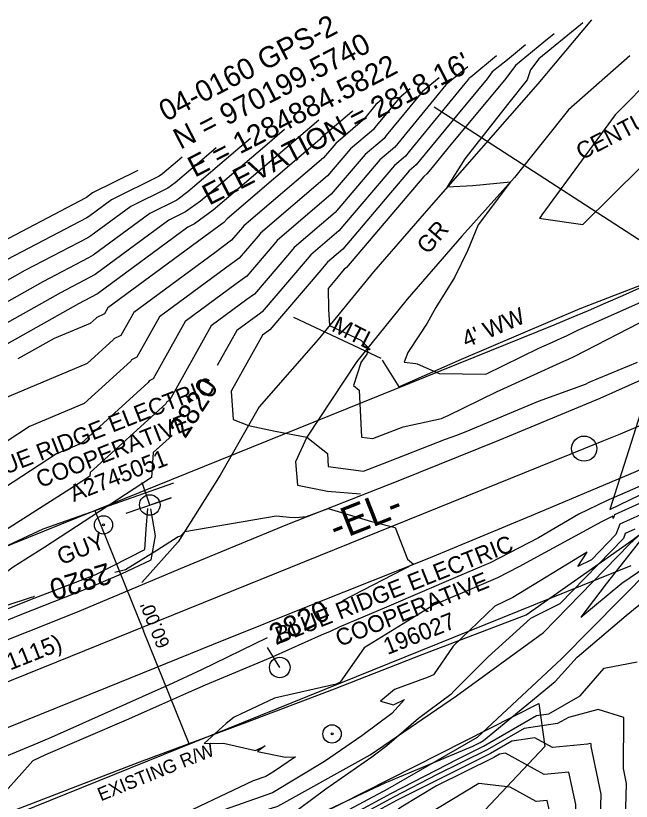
# Model space of a CAD drawing. Extents: x 1284446 to 1285480, y 969739 to 970628.
# Drawn here: x 1284710.8 to 1284857.4, y 970083.4 to 970270.6 of the extents above; entities that cross this region are included whole.
import ezdxf

# ---------------------------------------------------------------- set-up
doc = ezdxf.new("R2010")
doc.units = 0
for name, color, linetype in [('CTL Primary Horizontal and Vertical Leader', 7, 'Continuous'), ('CTL Primary Horizontal and Vertical Text', 7, 'Continuous'), ('Default', 7, 'Continuous'), ('Exist Horizontal Alignment', 7, 'Continuous'), ('Exist Horizontal Alignment Direction Label', 7, 'Continuous'), ('Exist Horizontal Alignment Point', 7, 'Continuous'), ('Exist Hydro Jurisdictional Stream or Body of Water', 7, 'Continuous'), ('Exist Other Culture Anchor (Guy Wire) CELL', 7, 'Continuous'), ('Exist Other Culture Fence Line', 7, 'Continuous'), ('Exist Other Culture Fence Line Text', 7, 'Continuous'), ('Exist Other Culture Gate', 7, 'Continuous'), ('Exist Other Culture Gate Text', 7, 'Continuous'), ('Exist Other Culture Located Object Text', 7, 'Continuous'), ('Exist Right of Way Line', 7, 'Continuous'), ('Exist Right of Way Line Text', 7, 'Continuous'), ('Exist Right of Way Width CELL', 7, 'Continuous'), ('Exist Roads EOP', 7, 'Continuous'), ('Exist Roads EOP Text', 7, 'Continuous'), ('Exist Roads Soil', 7, 'Continuous'), ('Exist Roads Soil Text', 7, 'Continuous'), ('Exist Utilities Power Joint Use Telephone CELL', 7, 'Continuous'), ('Exist Utilities Power Joint Use Telephone Text', 7, 'Continuous'), ('Exist Utilities Power Pole CELL', 7, 'Continuous'), ('Exist Utilities Power Pole Text', 7, 'Continuous'), ('Exist Utilities Telephone Pole Text', 7, 'Continuous'), ('Exist Utilities Telephone UG Cable SUE LOS D', 7, 'Continuous'), ('Exist Vegetation Woods Line', 7, 'Continuous')]:
    doc.layers.add(name, color=color, linetype=linetype)

msp = doc.modelspace()

# ---------------------------------------------------------------- linework, layer by layer
at = {"layer": 'CTL Primary Horizontal and Vertical Leader'}
msp.add_line((1284882.18, 970202.31), (1284810.44, 970248.87), dxfattribs=at)
at = {"layer": 'Default'}
for points in [[(1284845.89, 970268.91), (1284845.33, 970268.46), (1284835.4, 970260.35), (1284833.44, 970257.71), (1284832.64, 970255.39), (1284827.89, 970249.49), (1284817.77, 970236.54), (1284813.59, 970229.83), (1284819.68, 970230.14), (1284828.68, 970231.07), (1284820.96, 970220.8), (1284818.37, 970214.62), (1284815.31, 970208.23), (1284810.87, 970201.12), (1284808.77, 970197.34), (1284804.53, 970190.84), (1284804.16, 970190.36), (1284803.35, 970188.1), (1284806.1, 970187.73), (1284806.39, 970187.69), (1284811.67, 970185.39), (1284822.75, 970185.21), (1284835.4, 970191.39), (1284837.95, 970192.55), (1284841.62, 970194.18), (1284841.82, 970194.28), (1284844.67, 970195.74), (1284869.18, 970206.6)], [(1284839.04, 970266.29), (1284836.61, 970264.31), (1284829.85, 970258.79), (1284827.54, 970255.68), (1284813.75, 970239.1), (1284809.97, 970234.48), (1284808.72, 970232.97), (1284807.97, 970232.34), (1284789.57, 970210.67), (1284789.04, 970210.21), (1284787.21, 970208), (1284785.2, 970205.66), (1284785.26, 970200.75), (1284785.53, 970196.81), (1284793.01, 970193.3), (1284794.77, 970191.58), (1284794.41, 970189.99), (1284792.99, 970188.03), (1284792.98, 970187.94), (1284791.25, 970182.51), (1284792.61, 970181.44), (1284793.11, 970170.24), (1284795.87, 970169.86), (1284803.06, 970172.65), (1284812.24, 970174.65), (1284812.72, 970174.89), (1284813.81, 970175.39), (1284825.34, 970181.03), (1284841.34, 970188.29), (1284842.5, 970188.8), (1284843.81, 970189.47), (1284862.01, 970198.79)], [(1284832.19, 970263.67), (1284827.89, 970260.16), (1284824.3, 970257.24), (1284823.08, 970255.59), (1284815.77, 970246.8), (1284807.24, 970236.37), (1284806.17, 970235.08), (1284804.48, 970233.65), (1284788.67, 970215.03), (1284785.05, 970211.93), (1284783.47, 970210.02), (1284771.27, 970195.78), (1284770.98, 970195.57), (1284769.6, 970194.54), (1284762.1, 970181.14), (1284762.58, 970174.45), (1284766.24, 970173), (1284772.58, 970171.62), (1284780.12, 970170.21), (1284780.13, 970170.2), (1284785.05, 970166.35), (1284785.19, 970163.25), (1284793.63, 970162.11), (1284798.15, 970163.86), (1284813.18, 970169.72), (1284815.88, 970170.66), (1284818.12, 970171.59), (1284835.35, 970178.78), (1284846.49, 970182.87), (1284847.39, 970183.34), (1284858.91, 970188.12)], [(1284825.33, 970261.06), (1284819.16, 970256.02), (1284818.75, 970255.68), (1284818.61, 970255.5), (1284817.78, 970254.5), (1284804.52, 970238.27), (1284803.62, 970237.19), (1284800.99, 970234.96), (1284787.76, 970219.38), (1284781.06, 970213.66), (1284779.73, 970212.05), (1284769.46, 970200.05), (1284768.42, 970199.29), (1284763.45, 970195.63), (1284758.78, 970187.27)], [(1284818.48, 970258.44), (1284813.21, 970254.13), (1284801.79, 970240.16), (1284801.07, 970239.3), (1284797.5, 970236.28), (1284786.85, 970223.74), (1284777.07, 970215.38), (1284775.99, 970214.07), (1284767.64, 970204.32), (1284765.86, 970203.01), (1284757.3, 970196.71), (1284747.37, 970178.93), (1284746.78, 970178.64), (1284746.5, 970178.13), (1284728.47, 970161.78), (1284728.41, 970160.88), (1284726.52, 970159.64), (1284724.54, 970158.35), (1284703.64, 970145.09)], [(1284863.19, 970256.67), (1284853.55, 970247.05), (1284836.13, 970223.15), (1284835.89, 970222.82), (1284835.88, 970222.81), (1284835.56, 970222.37), (1284836.53, 970222.24), (1284845.9, 970220.91), (1284859.84, 970234.71)], [(1284811.63, 970255.82), (1284807.66, 970252.58), (1284799.06, 970242.06), (1284798.52, 970241.41), (1284794.01, 970237.59), (1284785.94, 970228.09), (1284773.09, 970217.1), (1284772.25, 970216.1), (1284765.83, 970208.59), (1284763.3, 970206.73), (1284751.16, 970197.79), (1284743.51, 970184.1), (1284742.57, 970183.64), (1284742.36, 970183.24), (1284726.36, 970168.74), (1284720.49, 970166.27), (1284697.97, 970151.55)], [(1284804.78, 970253.2), (1284802.11, 970251.02), (1284796.33, 970243.96), (1284795.97, 970243.52), (1284790.52, 970238.9), (1284785.04, 970232.45), (1284769.1, 970218.82), (1284768.52, 970218.12), (1284764.01, 970212.86), (1284760.74, 970210.45), (1284745.01, 970198.87), (1284739.64, 970189.26), (1284738.36, 970188.63), (1284738.21, 970188.36), (1284727.07, 970178.26), (1284714.06, 970172.78), (1284700.58, 970163.97)], [(1284797.93, 970250.58), (1284796.56, 970249.47), (1284793.61, 970245.85), (1284793.42, 970245.63), (1284787.02, 970240.21), (1284784.13, 970236.8), (1284765.11, 970220.55), (1284764.78, 970220.14), (1284762.2, 970217.13), (1284758.18, 970214.17), (1284738.87, 970199.95), (1284735.78, 970194.43), (1284734.15, 970193.63), (1284734.06, 970193.48), (1284727.79, 970187.79), (1284707.63, 970179.29)], [(1284791.08, 970247.96), (1284791.01, 970247.91), (1284790.88, 970247.75), (1284790.87, 970247.74), (1284783.53, 970241.52), (1284783.22, 970241.16), (1284761.12, 970222.27), (1284761.04, 970222.17), (1284760.38, 970221.4), (1284755.62, 970217.9), (1284732.72, 970201.03), (1284731.92, 970199.6), (1284729.94, 970198.63), (1284729.92, 970198.59), (1284728.51, 970197.31), (1284719.91, 970193.69), (1284711.26, 970188.85)], [(1284782.99, 970245.74), (1284777.01, 970240.66), (1284757.78, 970224.29), (1284753.36, 970221.03), (1284751.76, 970220.24), (1284730.23, 970204.39), (1284728.57, 970203.46), (1284725.7, 970201.95), (1284703.48, 970189.51)], [(1284774.84, 970243.54), (1284770.08, 970239.49), (1284754.77, 970226.46), (1284751.25, 970223.87), (1284747.23, 970221.88), (1284729.7, 970208.98), (1284728.36, 970208.22), (1284721.46, 970204.6), (1284702.83, 970194.17)], [(1284766.69, 970241.34), (1284763.15, 970238.33), (1284751.75, 970228.63), (1284749.13, 970226.7), (1284742.69, 970223.51), (1284729.18, 970213.57), (1284728.14, 970212.98), (1284717.21, 970207.24), (1284702.18, 970198.82)], [(1284758.54, 970239.14), (1284756.22, 970237.16), (1284748.74, 970230.8), (1284747.02, 970229.54), (1284738.16, 970225.14), (1284728.66, 970218.15), (1284727.93, 970217.74), (1284712.97, 970209.89), (1284701.53, 970203.48)], [(1284750.39, 970236.94), (1284749.29, 970236), (1284745.73, 970232.97), (1284744.91, 970232.37), (1284733.62, 970226.77), (1284728.14, 970222.74), (1284727.72, 970222.5), (1284708.72, 970212.53), (1284700.87, 970208.14), (1284698.91, 970206.2), (1284696.12, 970203.72), (1284683.01, 970190.92), (1284669.6, 970179.36)], [(1284739.84, 970233.74), (1284729.08, 970228.4), (1284727.62, 970227.33), (1284727.51, 970227.26), (1284704.48, 970215.18), (1284700.22, 970212.79), (1284697.9, 970210.5), (1284696.24, 970209.02), (1284680.37, 970193.53), (1284669.07, 970183.79), (1284663.63, 970178.84), (1284655.84, 970171.76), (1284643.02, 970159.37), (1284642.05, 970158.93), (1284625.37, 970148.84), (1284617.73, 970145.52), (1284604.5, 970139.27), (1284601.13, 970138.8), (1284580.23, 970128.69), (1284573.36, 970127.93), (1284568.84, 970128.73)], [(1284748.03, 970170.64), (1284743.49, 970166.53), (1284743.11, 970160.61), (1284730.72, 970152.47), (1284717.68, 970144.01), (1284710.17, 970139.24), (1284709.56, 970138.79), (1284691.19, 970125.24), (1284702.36, 970128.13), (1284714.55, 970132.09), (1284714.9, 970132.2), (1284715.19, 970132.29), (1284715.26, 970132.31)], [(1284860.83, 970159.08), (1284851.5, 970155.03), (1284844.93, 970151.86), (1284835.32, 970146.2), (1284823.82, 970140.28), (1284822.27, 970139.61), (1284815.57, 970136.76), (1284799.1, 970129.73), (1284787.86, 970124.9), (1284785.7, 970123.93), (1284783.51, 970123.01), (1284771.83, 970117.8), (1284755.92, 970111.13), (1284751.92, 970109.35), (1284745.5, 970106.55), (1284737.05, 970102.79), (1284717.87, 970094.48), (1284714.86, 970093.11), (1284708.34, 970085.8)], [(1284865.15, 970152.41), (1284863.74, 970150.95), (1284858.15, 970143.83), (1284857.93, 970143.55), (1284851.44, 970135.29), (1284845.39, 970127.31), (1284855.19, 970135.46), (1284860.88, 970139.28), (1284861.21, 970139.54), (1284870.02, 970144.7), (1284875.33, 970148.62), (1284884.51, 970153.12), (1284887.68, 970155.16), (1284888.77, 970156.05), (1284888.78, 970156.01), (1284890.6, 970152.24), (1284888.81, 970146.6), (1284891.3, 970150.92), (1284891.58, 970151.55)], [(1284859.37, 970154.43), (1284853.43, 970151.74), (1284853.08, 970150.83), (1284853.01, 970151.39), (1284850.35, 970150), (1284830.62, 970139.32), (1284825.53, 970136.69), (1284817.17, 970133.11), (1284816.66, 970132.89), (1284815.43, 970132.37), (1284810.33, 970130.17), (1284793.78, 970119.98), (1284788.05, 970111.8), (1284787.12, 970111.33), (1284772.41, 970108.01), (1284762.81, 970103.53), (1284760.88, 970101.98), (1284755.64, 970097.22), (1284760.29, 970097.26), (1284767.89, 970095.53), (1284770.17, 970096.68), (1284768.37, 970095.35), (1284775.02, 970093.93), (1284777.42, 970094.05), (1284772.44, 970090.62), (1284770.32, 970089.35), (1284767.37, 970088.3), (1284746.65, 970078.45)], [(1284734.41, 970138.02), (1284736.92, 970138.68), (1284744.35, 970143.25), (1284749.48, 970146.58), (1284750.13, 970146.71), (1284751.04, 970147.76), (1284772.82, 970151.48), (1284776.02, 970151.12), (1284777.51, 970151.04), (1284780.08, 970151.33), (1284785.19, 970153.22), (1284795.55, 970150.1), (1284801.18, 970148.68), (1284804.12, 970141.13), (1284805.57, 970139.95), (1284788.59, 970131.25)], [(1284859.6, 970151.72), (1284854.71, 970149.49), (1284853.74, 970146.99), (1284847.92, 970141), (1284844.71, 970139.39), (1284846.93, 970142.78), (1284829.23, 970131.97), (1284824.92, 970129.98), (1284814.97, 970120.43), (1284810.29, 970113.61), (1284809.06, 970113.04), (1284801.01, 970110.11), (1284797.67, 970107.34), (1284800.75, 970106.41), (1284803.41, 970107.68), (1284800.35, 970104.39), (1284793.21, 970099.03), (1284784.32, 970092.92), (1284771.92, 970085.47), (1284754.76, 970079.39)], [(1284858.27, 970148.29), (1284855.99, 970147.25), (1284855.54, 970146.09), (1284840.4, 970130.49), (1284833.4, 970126.99), (1284823.3, 970117.89), (1284815.21, 970109.79), (1284814.41, 970108.93), (1284806.71, 970103.16), (1284799.18, 970096.63), (1284795.58, 970093.93), (1284784.68, 970086.3), (1284775.07, 970079.22)], [(1284782.76, 970080.33), (1284798.81, 970087.84), (1284819.64, 970096.55), (1284821.27, 970097.39), (1284821.41, 970097.46), (1284822.19, 970097.92), (1284839.25, 970112.01), (1284844.55, 970117.79), (1284856.22, 970127.75), (1284864.85, 970134.79)], [(1284770.67, 970122.38), (1284755.04, 970114.8), (1284747.18, 970111.12), (1284744.66, 970109.99), (1284744.6, 970109.97), (1284719.18, 970098.66), (1284717.11, 970097.76), (1284716.01, 970097.26), (1284707.63, 970093.8), (1284683.78, 970082.51), (1284682.67, 970081.27), (1284681.13, 970080.8), (1284680.2, 970080.2)], [(1284781.36, 970075.12), (1284800.31, 970085.41), (1284816.16, 970093.56), (1284822.23, 970096.58), (1284834.81, 970103.89), (1284837.78, 970104.31), (1284845.27, 970108.59), (1284850.95, 970115.2), (1284858.84, 970116.67)], [(1284855.82, 970070.4), (1284856.31, 970087.69), (1284855.55, 970091.25), (1284855.64, 970103.39), (1284849.51, 970105.3), (1284842.46, 970103.44), (1284839.88, 970101.97), (1284831.87, 970100.82), (1284823.05, 970095.69), (1284811.04, 970089.73), (1284800.91, 970084.52), (1284788.79, 970077.94)], [(1284849.79, 970068.77), (1284850.26, 970085.18), (1284847.87, 970096.47), (1284847.87, 970097.12), (1284847.55, 970097.22), (1284846.98, 970097.07), (1284838.62, 970096.24), (1284834.42, 970098.54), (1284828.94, 970097.75), (1284823.87, 970094.81), (1284805.92, 970085.9), (1284801.51, 970083.63), (1284796.23, 970080.76)], [(1284842, 970058.21), (1284842.75, 970060.15), (1284843.9, 970062.31), (1284843.91, 970072.05), (1284844.21, 970082.67), (1284842.57, 970090.4), (1284836.68, 970089.82), (1284827.42, 970094.89), (1284826, 970094.69), (1284824.69, 970093.92), (1284811.04, 970087.15), (1284802.57, 970082.04), (1284785.82, 970069.23), (1284784.71, 970068.14)], [(1284835.1, 970054.15), (1284836.25, 970057.13), (1284838.01, 970060.43), (1284838.02, 970075.34), (1284838.16, 970080.15), (1284837.41, 970083.66), (1284834.74, 970083.4), (1284828.56, 970086.79), (1284821.11, 970087.68), (1284805.22, 970078.1), (1284794.34, 970069.77), (1284785.7, 970061.35), (1284779.71, 970059.61), (1284777.89, 970059.07), (1284758.44, 970049.57), (1284755.9, 970048.46), (1284748.28, 970046.25), (1284727.72, 970037.01), (1284725.28, 970036.25), (1284723.69, 970035.84), (1284717.37, 970033.86), (1284695.06, 970028.05)]]:
    msp.add_lwpolyline(points, dxfattribs=at)
at = {"layer": 'Exist Horizontal Alignment'}
msp.add_line((1284591.83, 970064.7), (1284846.18, 970167.48), dxfattribs=at)
msp.add_arc((1284607.88, 970757.2), 636.05, 292.00278, 305.45278, dxfattribs=at)
at = {"layer": 'Exist Horizontal Alignment Point'}
msp.add_circle((1284846.18, 970167.48), 3, dxfattribs=at)
at = {"layer": 'Exist Hydro Jurisdictional Stream or Body of Water'}
for points in [[(1284608.58, 970014.06), (1284652.45, 970028.03), (1284689.07, 970040.96), (1284720.23, 970048.49), (1284751.74, 970066.17), (1284777.43, 970074.66), (1284799.45, 970086.45), (1284820.82, 970098.72), (1284840.81, 970117.42), (1284861.95, 970138.73), (1284875.04, 970148.73), (1284887.31, 970157.71)], [(1284608.31, 970022.37), (1284646.2, 970034.88), (1284690.96, 970050.11), (1284715.91, 970057.86), (1284748.8, 970074.52), (1284773.24, 970082.29), (1284795.23, 970094.54), (1284815.77, 970108.56), (1284836.54, 970123.66), (1284856.99, 970144.69), (1284864.89, 970151.94), (1284873.19, 970156.9)]]:
    msp.add_lwpolyline(points, dxfattribs=at)
at = {"layer": 'Exist Other Culture Anchor (Guy Wire) CELL'}
for centre, radius in [((1284731.68, 970149.31), 2.18), ((1284731.68, 970149.31), 0.24), ((1284786.13, 970099.5), 2.18), ((1284786.13, 970099.5), 0.24)]:
    msp.add_circle(centre, radius, dxfattribs=at)
at = {"layer": 'Exist Other Culture Fence Line'}
for points in [[(1284798.04, 970188.58), (1284802.02, 970182.24), (1284816.97, 970188.81), (1284845.25, 970200.84), (1284869.92, 970210.38), (1284879.4, 970214.23), (1284891.22, 970210.43)], [(1284748.36, 970159.23), (1284717.21, 970148.3), (1284693.29, 970137.2), (1284650.97, 970121.07)], [(1284601.96, 970038.43), (1284640.3, 970053.54), (1284684.75, 970071.66), (1284706.29, 970079.75), (1284740.35, 970092.84), (1284765.34, 970102.18), (1284786.69, 970110.23), (1284807.57, 970118.44), (1284832.39, 970127.91), (1284856.77, 970145.02), (1284872.83, 970156.87)]]:
    msp.add_lwpolyline(points, dxfattribs=at)
at = {"layer": 'Exist Other Culture Gate'}
msp.add_line((1284776.94, 970198.78), (1284797.76, 970189.02), dxfattribs=at)
at = {"layer": 'Exist Other Culture Located Object Text'}
for p, q in [((1284864.82, 970192.39), (1284852.28, 970153.01)), ((1284852.28, 970153.01), (1284909.05, 970180.44))]:
    msp.add_line(p, q, dxfattribs=at)
at = {"layer": 'Exist Right of Way Line'}
for p, q in [((1284580.59, 970092.51), (1284834.94, 970195.29)), ((1284603.06, 970036.88), (1284857.42, 970139.66))]:
    msp.add_line(p, q, dxfattribs=at)
msp.add_arc((1284607.88, 970757.2), 606.05, 292.00278, 305.45278, dxfattribs=at)
at = {"layer": 'Exist Right of Way Width CELL'}
for p in [(1284729.65, 970152.75), (1284752.13, 970097.12)]:
    msp.add_line(p, (1284741.23, 970124.08), dxfattribs=at)
at = {"layer": 'Exist Roads EOP'}
for points in [[(1284588.17, 970073.97), (1284609.91, 970082.54), (1284630.17, 970090.65), (1284654.44, 970100.5), (1284678.03, 970109.93), (1284701.92, 970119.24), (1284725.51, 970128.63), (1284750.96, 970139.34), (1284775.61, 970149.46), (1284801.89, 970159.77), (1284826.13, 970169.58), (1284850.02, 970179.49), (1284870.96, 970188.88), (1284892.26, 970198.92), (1284892.63, 970199.46)], [(1284594.23, 970054.93), (1284616.52, 970063.71), (1284637.53, 970072.23), (1284661.54, 970081.97), (1284684.2, 970091.02), (1284708.29, 970100.77), (1284732.61, 970110.68), (1284757.85, 970120.85), (1284782.44, 970130.77), (1284809.22, 970141.4), (1284833.63, 970151.55), (1284857.38, 970161.54), (1284879.44, 970171.07), (1284883.53, 970171.7)]]:
    msp.add_lwpolyline(points, dxfattribs=at)
at = {"layer": 'Exist Roads Soil'}
for points in [[(1284847.92, 970269.69), (1284835.17, 970254.44), (1284821.63, 970238.99), (1284808.61, 970224.15), (1284796.03, 970209.59), (1284782.81, 970193.51), (1284768.73, 970177.4), (1284759.51, 970161.13), (1284749.49, 970145.31), (1284740.82, 970135.59)], [(1284857.11, 970261.11), (1284842.43, 970248.21), (1284829.57, 970232.07), (1284817.04, 970218.11), (1284804.05, 970203.09), (1284792.06, 970188.21), (1284780.13, 970170.23), (1284777.45, 970164.32), (1284777.92, 970158.77), (1284785.08, 970157.31), (1284792.88, 970156.68)]]:
    msp.add_lwpolyline(points, dxfattribs=at)
at = {"layer": 'Exist Utilities Power Joint Use Telephone CELL'}
msp.add_line((1284742.71, 970154.05), (1284742.71, 970154.05), dxfattribs=at)
msp.add_lwpolyline([(1284737.1, 970152.11), (1284747.83, 970155.78), (1284742.72, 970154.03), (1284740.88, 970159.37)], dxfattribs=at)
msp.add_circle((1284742.71, 970154.06), 2.45, dxfattribs=at)
at = {"layer": 'Exist Utilities Power Pole CELL'}
for q in [(1284770.72, 970120.12), (1284773.68, 970115.33)]:
    msp.add_line((1284773.68, 970115.33), q, dxfattribs=at)
msp.add_circle((1284773.68, 970115.33), 2.45, dxfattribs=at)
at = {"layer": 'Exist Utilities Telephone UG Cable SUE LOS D'}
for points in [[(1284574.8, 970074.26), (1284594.5, 970082.54), (1284616.05, 970091.44), (1284632.57, 970100.26), (1284654.25, 970107.71), (1284668.02, 970113.22), (1284683.01, 970118.85), (1284698.34, 970125.18), (1284715.18, 970131.84), (1284729.87, 970137.49), (1284741.49, 970143.41), (1284741.82, 970148.26), (1284742.26, 970153.18)], [(1284576.08, 970071.21), (1284596.07, 970079.34), (1284617.42, 970089.61), (1284633.49, 970097.01), (1284654.93, 970104.42), (1284670.21, 970110.81), (1284685.4, 970117.07), (1284700.9, 970123.39), (1284712.2, 970128.05), (1284727.98, 970134.25), (1284736, 970137.68), (1284743.05, 970140.96), (1284744.07, 970146.74), (1284742.92, 970153.14)]]:
    msp.add_lwpolyline(points, dxfattribs=at)
at = {"layer": 'Exist Vegetation Woods Line'}
msp.add_lwpolyline([(1284756.79, 970066.82), (1284776.33, 970076.8), (1284835.4, 970106.74), (1284836.86, 970096.51), (1284812.24, 970070.36), (1284780.66, 970046.59), (1284759.93, 970045.08), (1284756.79, 970066.82)], dxfattribs=at)

# ---------------------------------------------------------------- texts
at = {"layer": 'CTL Primary Horizontal and Vertical Text'}
for s, p in [('04-0160 GPS-2', (1284746.56, 970245.33)), ('N = 970199.5740', (1284750, 970238.67)), ("ELEVATION = 2818.16'", (1284756.88, 970225.34)), ('E = 1284884.5822', (1284753.44, 970232.01))]:
    msp.add_text(s, height=5, rotation=27.3235, dxfattribs=at).set_placement(p)
at = {"layer": 'Default'}
for rotation, p in [(57.1183, (1284751.14, 970169.67)), (196.6108, (1284732.64, 970140.34)), (26.3241, (1284772.73, 970120.56))]:
    msp.add_text('2820', height=5, rotation=rotation, dxfattribs=at).set_placement(p)
at = {"layer": 'Exist Horizontal Alignment Direction Label'}
msp.add_text('-EL-', height=7, rotation=21.5608, dxfattribs=at).set_placement((1284787.06, 970145.26))
at = {"layer": 'Exist Other Culture Anchor (Guy Wire) CELL'}
msp.add_text('GUY', height=4, rotation=21.458, dxfattribs=at).set_placement((1284721.6, 970139.68))
at = {"layer": 'Exist Other Culture Fence Line Text'}
msp.add_text("4' WW", height=4, rotation=23.0478, dxfattribs=at).set_placement((1284818.13, 970191.47))
at = {"layer": 'Exist Other Culture Gate Text'}
msp.add_text('MTL', height=4, rotation=333.037, dxfattribs=at).set_placement((1284785.77, 970195.64))
at = {"layer": 'Exist Right of Way Line Text'}
msp.add_text('EXISTING R/W', height=3.2, rotation=22.0028, dxfattribs=at).set_placement((1284731.06, 970083.43))
at = {"layer": 'Exist Right of Way Width CELL'}
msp.add_text("60.00'", height=3.2, rotation=112.0028, dxfattribs=at).set_placement((1284747.58, 970120.73))
at = {"layer": 'Exist Roads EOP Text'}
msp.add_text('FRANK DILLARD RD. (SR 1115)', height=4, rotation=21.6942, dxfattribs=at).set_placement((1284648.99, 970090.54))
at = {"layer": 'Exist Roads Soil Text'}
msp.add_text('GR', height=4, rotation=49.1186, dxfattribs=at).set_placement((1284808.96, 970213.55))
at = {"layer": 'Exist Utilities Power Joint Use Telephone Text'}
for s, p in [('BLUE RIDGE ELECTRIC', (1284702.27, 970158.87)), ('COOPERATIVE', (1284716.59, 970158.05)), ('A2745051', (1284724.57, 970154.74))]:
    msp.add_text(s, height=4, rotation=21.458, dxfattribs=at).set_placement(p)
at = {"layer": 'Exist Utilities Power Pole Text'}
for s, p in [('BLUE RIDGE ELECTRIC', (1284773.62, 970120.97)), ('COOPERATIVE', (1284787.93, 970120.21)), ('196027', (1284799.33, 970118.28))]:
    msp.add_text(s, height=4, rotation=21.6814, dxfattribs=at).set_placement(p)
at = {"layer": 'Exist Utilities Telephone Pole Text'}
msp.add_text('CENTURY LINK', height=4, rotation=27.3235, dxfattribs=at).set_placement((1284845.58, 970236.14))

doc.saveas('drawing.dxf')
